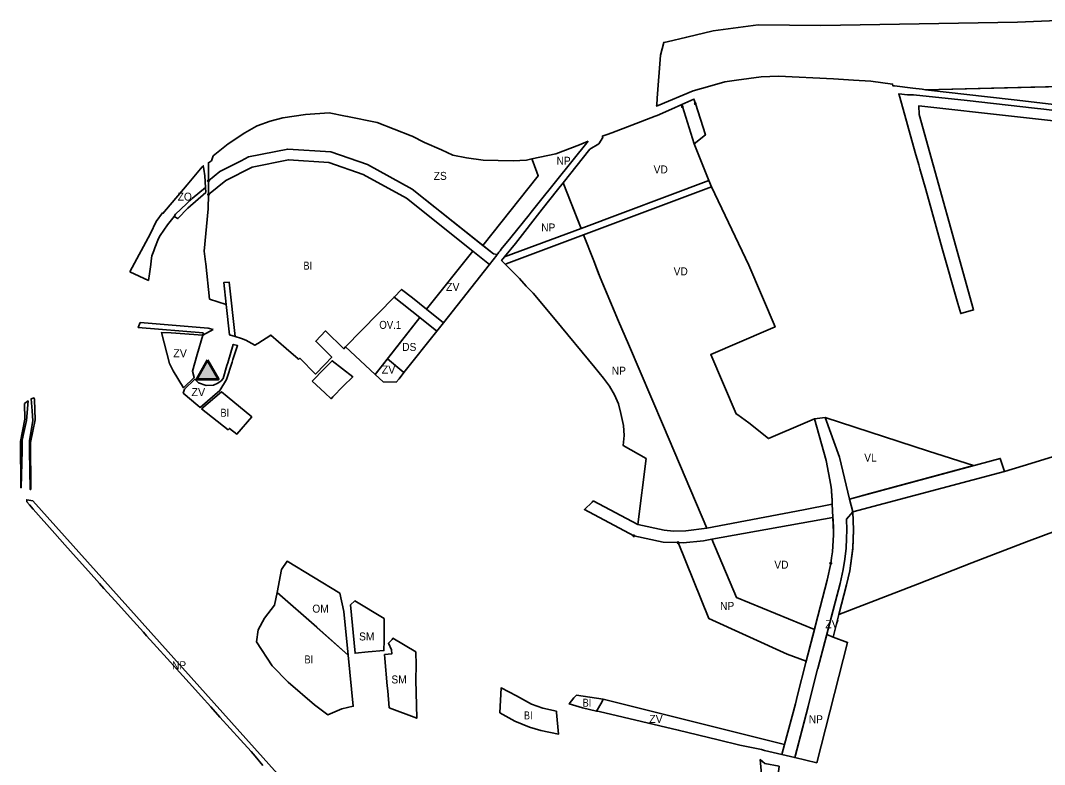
# Model space of a CAD drawing. Extents: x -650276 to -642489, y -1074311 to -1066720.
# Drawn here: x -650276 to -648741, y -1070281 to -1069165 of the extents above; entities that cross this region are included whole.
import ezdxf

# ---------------------------------------------------------------- set-up
doc = ezdxf.new("R2010")
doc.units = 0
doc.header["$LTSCALE"] = 4.8
doc.header["$PDMODE"] = 32
doc.header["$PDSIZE"] = 2.4
for name, color, linetype, lineweight in [('11', 7, 'Continuous', 35), ('12', 7, 'Continuous', 35), ('13', 7, 'Continuous', 35), ('15', 7, 'Continuous', 35), ('18', 7, 'Continuous', 35), ('2', 7, 'Continuous', 35), ('24', 7, 'Continuous', 35), ('25', 7, 'Continuous', 35), ('34', 7, 'Continuous', 35), ('35', 7, 'Continuous', 35), ('40', 7, 'Continuous', 35), ('41', 7, 'Continuous', 35), ('42', 7, 'Continuous', 35), ('48', 7, 'Continuous', 35), ('55', 7, 'Continuous', 53)]:
    doc.layers.add(name, color=color, linetype=linetype, lineweight=lineweight)
doc.layers.add('62', color=7, linetype='Continuous')

msp = doc.modelspace()

# ---------------------------------------------------------------- hatches: boundary and pattern name
at = {"layer": '55'}
msp.add_hatch(color=256, dxfattribs=at).paths.add_polyline_path([(-649995.793, -1069674.354), (-650011.744, -1069703), (-649979.36, -1069703)])

# ---------------------------------------------------------------- linework, layer by layer
at = {"layer": '11'}
msp.add_lwpolyline([(-649788.91, -1069654.4), (-649744.517, -1069695.746), (-649677.124, -1069610.681), (-649715.908, -1069579.804)], close=True, dxfattribs=at)
at = {"layer": '12'}
msp.add_lwpolyline([(-649891.21, -1070022.68), (-649832.007, -1070074.751), (-649784.87, -1070116.76), (-649791.31, -1070051.51), (-649797.45, -1070023.77), (-649876.31, -1069975.93), (-649884.59, -1069988.57)], close=True, dxfattribs=at)
at = {"layer": '13'}
msp.add_lwpolyline([(-648722.24, -1069817.54), (-648772.48, -1069832.83), (-648800.85, -1069841.52), (-649028.017, -1069902.109), (-649027.135, -1069928.902), (-649027.953, -1069955.702), (-649032.644, -1069990.371), (-649037.411, -1070011.659), (-649048.918, -1070055.852), (-648931.057, -1070010.171), (-648849.532, -1069978.559), (-648767.83, -1069946.87), (-648562.242, -1069870.301)], dxfattribs=at)
at = {"layer": '15', "lineweight": 25}
for p, q in [((-649971.446, -1069558.139), (-649963.498, -1069557.234)), ((-649971.446, -1069558.139), (-649967.81, -1069590.74)), ((-649963.498, -1069557.234), (-649954.365, -1069639.105))]:
    msp.add_line(p, q, dxfattribs=at)
at = {"layer": '15'}
msp.add_line((-649057.868, -1069910.51), (-649058.82, -1069890.548), dxfattribs=at)
for points in [[(-648725.82, -1069299.81), (-648741.58, -1069298.16), (-648755.56, -1069296.7), (-648856.68, -1069285.01), (-648937.2, -1069276.37), (-648945.96, -1069276.64), (-648959.11, -1069275.13), (-648957.74, -1069280), (-648934.38, -1069362.79), (-648929.16, -1069381.32), (-648927.37, -1069387.62), (-648927.38, -1069387.623), (-648918.65, -1069418.53), (-648893.86, -1069506.89), (-648870.76, -1069589.26), (-648867.62, -1069599.37), (-648866.17, -1069604.48), (-648847.097, -1069598.995), (-648928.347, -1069306.125), (-648929.112, -1069293.123), (-648642.241, -1069324.949)], [(-649561.17, -1069515.83), (-649566.951, -1069515.099), (-649688.625, -1069418.156), (-649755.971, -1069381.179), (-649810.846, -1069362.154), (-649875.434, -1069357.751), (-649934.363, -1069369.537), (-649945.397, -1069375.277), (-649977.239, -1069391.714), (-649994.329, -1069405.451)], [(-649994.293, -1069425.949), (-649968.465, -1069405.189), (-649929.015, -1069384.784), (-649874.391, -1069373.859)], [(-649874.391, -1069373.859), (-649814.067, -1069377.972), (-649762.488, -1069395.854), (-649697.525, -1069431.522), (-649598.004, -1069510.814), (-649572.972, -1069530.758)], [(-649994.329, -1069405.451), (-649994.329, -1069405.451), (-649994.293, -1069425.949), (-649994.293, -1069425.949)], [(-649431.761, -1069486.57), (-649240.202, -1069414.528), (-649244.08, -1069404.753), (-649435.578, -1069476.772), (-649550.53, -1069519.68)], [(-649548.881, -1069530.963), (-649547.733, -1069530.185), (-649431.761, -1069486.57)], [(-649572.972, -1069530.758), (-649561.91, -1069516.78), (-649561.17, -1069515.83)], [(-649550.53, -1069519.68), (-649554.83, -1069525), (-649551.32, -1069528.49), (-649549.69, -1069530.14), (-649548.881, -1069530.963)], [(-650096.627, -1069617.746), (-650099.55, -1069625.53), (-650002.39, -1069633.65)], [(-649987.49, -1069628.6), (-649994.913, -1069626.246), (-650096.627, -1069617.746)], [(-650002.39, -1069633.65), (-650002.65, -1069637.14), (-649987.49, -1069628.6)], [(-649417.234, -1069885.193), (-649418.94, -1069887.36), (-649430.515, -1069898.514), (-649356.458, -1069937.945)], [(-649246.81, -1069926.27), (-649278.492, -1069930.573), (-649296.851, -1069931.092), (-649310.738, -1069929.342), (-649350.222, -1069920.873), (-649417.234, -1069885.193)], [(-649058.82, -1069890.548), (-649101.89, -1069898.73), (-649246.81, -1069926.27)], [(-649289.95, -1069948.146), (-649282.437, -1069948.342), (-649251.805, -1069945.276), (-649239.635, -1069943.094), (-649057.868, -1069910.51)], [(-649356.458, -1069937.945), (-649312.646, -1069947.342), (-649289.95, -1069948.146)]]:
    msp.add_lwpolyline(points, dxfattribs=at)
for points in [[(-650025.31, -1069446.49), (-649998.512, -1069422.926), (-649999.01, -1069415.628), (-650018.873, -1069431.749), (-650043.521, -1069455.69), (-650045.72, -1069459.1), (-650040.012, -1069461.999)], [(-649967.81, -1069590.74), (-649962.71, -1069636.46), (-649954.365, -1069639.105), (-649963.498, -1069557.234), (-649971.446, -1069558.139)], [(-649677.124, -1069610.681), (-649651.846, -1069630.82), (-649641.978, -1069618.226), (-649667.188, -1069598.14), (-649688.446, -1069581.203), (-649704.646, -1069568.296), (-649715.908, -1069579.804)], [(-648800.85, -1069841.52), (-648806.946, -1069821.79), (-649032.928, -1069882.782), (-649028.017, -1069902.109)]]:
    msp.add_lwpolyline(points, close=True, dxfattribs=at)
for p in [(-649994.329, -1069405.451), (-649994.293, -1069425.949), (-649356.458, -1069937.945), (-649289.95, -1069948.146)]:
    msp.add_point(p, dxfattribs=at)
at = {"layer": '18'}
for points in [[(-649781.53, -1070041.2), (-649774.45, -1070113.92), (-649754.82, -1070111.89), (-649731.12, -1070109.96), (-649730.96, -1070094.91), (-649730.89, -1070088.96), (-649730.6, -1070061.98), (-649774.73, -1070035.58)], [(-649730.57, -1070115.76), (-649730, -1070122.01), (-649726.22, -1070162.75), (-649725.49, -1070170.64), (-649723.17, -1070195.81), (-649682.04, -1070211.58), (-649683.12, -1070154.14), (-649682.98, -1070132.1), (-649683.57, -1070112.05), (-649717.72, -1070091.61), (-649718.71, -1070093.35), (-649724.36, -1070099.03), (-649719.69, -1070108.94), (-649719.24, -1070114.87)]]:
    msp.add_lwpolyline(points, close=True, dxfattribs=at)
at = {"layer": '2'}
for points in [[(-649715.908, -1069579.804), (-649704.646, -1069568.296), (-649688.446, -1069581.203), (-649667.188, -1069598.14), (-649598.004, -1069510.814), (-649697.525, -1069431.522), (-649762.488, -1069395.854), (-649814.067, -1069377.972), (-649874.391, -1069373.859), (-649929.015, -1069384.784), (-649968.465, -1069405.189), (-649994.293, -1069425.949), (-649994.53, -1069447.61), (-650000.59, -1069511.15), (-649998.81, -1069527.07), (-649998.5, -1069529.88), (-649992.59, -1069582.88), (-649967.81, -1069590.74), (-649971.446, -1069558.139), (-649963.498, -1069557.234), (-649954.365, -1069639.105), (-649944.963, -1069642.085)], [(-649944.963, -1069642.085), (-649938.2, -1069644.23), (-649924.8, -1069652.19), (-649920.45, -1069649.53), (-649900.64, -1069636.78), (-649877.82, -1069656.83), (-649859.96, -1069672.53), (-649859.17, -1069673.22), (-649857.49, -1069671.46), (-649833.94, -1069695.24), (-649833.94, -1069695.24), (-649819.98, -1069680.92), (-649809.47, -1069670.13), (-649833.38, -1069646.08), (-649818.71, -1069630.64), (-649791.3, -1069657.21), (-649788.91, -1069654.4), (-649715.908, -1069579.804)]]:
    msp.add_lwpolyline(points, dxfattribs=at)
for points in [[(-649838.99, -1069706.15), (-649820.64, -1069687.33), (-649808.96, -1069675.34), (-649777.94, -1069699.2), (-649792.13, -1069713.65), (-649807.66, -1069729.46), (-649810.41, -1069732.28), (-649819.9, -1069723.61)], [(-650004.59, -1069747.27), (-649974.86, -1069721.96), (-649966.52, -1069728.87), (-649929.38, -1069759.65), (-649951.56, -1069785.42), (-649963, -1069776.7), (-649965, -1069778.7)], [(-649922.3, -1070096.9), (-649919.55, -1070079.01), (-649910.34, -1070061.29), (-649895.45, -1070042.15), (-649891.21, -1070022.68), (-649784.87, -1070116.76), (-649777.29, -1070193.57), (-649794.37, -1070197.2), (-649815.33, -1070206.63), (-649835.28, -1070191.27), (-649874.94, -1070157.19), (-649898.55, -1070132.9)], [(-649557.21, -1070203.53), (-649555.44, -1070165.91), (-649532.57, -1070178.08), (-649509.72, -1070190.24), (-649492.67, -1070196.34), (-649472.6, -1070201.15), (-649472.43, -1070202.9), (-649469.176, -1070235.365), (-649496, -1070230), (-649513, -1070225), (-649535, -1070216)], [(-649442.63, -1070176.69), (-649402.29, -1070182.92), (-649404.2, -1070187.43), (-649412.2, -1070200.71), (-649433.3, -1070195.89), (-649453.27, -1070190.02), (-649446.19, -1070180.76)]]:
    msp.add_lwpolyline(points, close=True, dxfattribs=at)
at = {"layer": '24'}
for p, q in [((-649283.702, -1069294.132), (-649265.774, -1069350.068)), ((-649058.858, -1069889.759), (-649057.868, -1069910.51)), ((-649057.134, -1069932.873), (-649057.868, -1069910.51))]:
    msp.add_line(p, q, dxfattribs=at)
for points in [[(-648721.315, -1069164.952), (-648781.015, -1069167.44), (-649076.02, -1069172.683), (-649169.781, -1069171.432), (-649237.512, -1069180.731), (-649277.021, -1069189.913), (-649306.455, -1069196.754), (-649311.633, -1069197.958), (-649316.47, -1069216.91), (-649321.32, -1069281.47), (-649322.09, -1069291.73), (-649322.22, -1069293.54), (-649319.72, -1069292.47), (-649267.5, -1069270.41), (-649242.5, -1069263.3), (-649220.18, -1069257.03), (-649202.63, -1069254.4), (-649165.62, -1069249.43), (-649139.63, -1069248.73), (-649056.95, -1069252.55), (-649026.955, -1069254.366), (-649001.3, -1069255.92), (-648968.49, -1069260.36), (-648968.05, -1069263.06), (-648965.8, -1069262.75), (-648937.91, -1069266.51), (-648924.13, -1069268.21), (-648918.889, -1069268.875), (-648673.267, -1069262.895)], [(-649264.156, -1069289.589), (-649266.331, -1069282.804), (-649284.695, -1069291.033), (-649283.702, -1069294.132)], [(-649265.774, -1069350.068), (-649249.069, -1069336.66), (-649264.156, -1069289.589)], [(-649061.138, -1069979.243), (-649061.138, -1069979.243), (-649061.139, -1069979.254), (-649066.487, -1070004.267), (-649098.65, -1070127.795), (-649110.925, -1070177.113), (-649114.174, -1070189.816), (-649130.712, -1070250.935), (-649134.294, -1070266.095), (-649115.159, -1070270.568), (-649095.152, -1070193.731), (-649093.095, -1070186.132), (-649095.152, -1070193.731), (-649080.924, -1070137.409), (-649080.38, -1070136.996), (-649047.131, -1070009.304), (-649042.468, -1069988.477), (-649042.468, -1069988.477), (-649039.966, -1069973.035), (-649037.98, -1069956.626), (-649037.322, -1069942.129), (-649037.137, -1069928.996), (-649037.665, -1069912.977), (-649028.017, -1069902.109), (-649032.928, -1069882.782), (-649048, -1069820), (-649069.4, -1069760.67), (-649085.41, -1069762.44), (-649068, -1069825.147), (-649060.897, -1069861.994)]]:
    msp.add_lwpolyline(points, dxfattribs=at)
msp.add_lwpolyline([(-649701.211, -1069692.826), (-649651.773, -1069630.879), (-649677.124, -1069610.681), (-649726.033, -1069672.415)], close=True, dxfattribs=at)
for centre, radius, start, end in [((-649633.43, -1069918.001), 575.266, 2.81398, 5.58706), ((-649347.129, -1069931.193), 290, 350.46253, 4.08974), ((-649347.129, -1069931.193), 290, 359.66809, 4.08974)]:
    msp.add_arc(centre, radius, start, end, dxfattribs=at)
for p in [(-649283.702, -1069294.132), (-649264.156, -1069289.589)]:
    msp.add_point(p, dxfattribs=at)
at = {"layer": '25'}
msp.add_lwpolyline([(-648730.66, -1069290.43), (-648656.242, -1069297.116), (-648673.267, -1069262.895), (-648761.189, -1069265.035), (-648918.889, -1069268.875), (-648909.86, -1069270.02), (-648861.49, -1069275.34), (-648785.92, -1069284.2), (-648730.66, -1069290.43)], close=True, dxfattribs=at)
at = {"layer": '34'}
msp.add_line((-649032.928, -1069882.782), (-649002.558, -1069874.585), dxfattribs=at)
for points in [[(-649002.558, -1069874.585), (-648846.924, -1069832.58), (-648914.48, -1069810.75), (-649069.4, -1069760.67)], [(-649069.4, -1069760.67), (-649048, -1069820), (-649032.928, -1069882.782)]]:
    msp.add_lwpolyline(points, dxfattribs=at)
at = {"layer": '35'}
msp.add_line((-649202.375, -1070030.469), (-649085.737, -1070078.201), dxfattribs=at)
for points in [[(-649283.702, -1069294.132), (-649284.695, -1069291.033), (-649300.133, -1069297.95), (-649321.69, -1069307.61)], [(-649244.08, -1069404.753), (-649265.774, -1069350.068), (-649283.702, -1069294.132)], [(-649321.69, -1069307.61), (-649324.3, -1069308.59), (-649359.48, -1069321.82), (-649389.4, -1069333.35), (-649396.52, -1069336.09), (-649403.92, -1069338.26)], [(-649403.92, -1069338.26), (-649403.03, -1069340.66), (-649408.81, -1069349.89), (-649422.19, -1069357.99), (-649462.25, -1069408.32), (-649435.578, -1069476.772), (-649244.08, -1069404.753)], [(-649060.897, -1069861.994), (-649068, -1069825.147), (-649085.41, -1069762.44), (-649085.41, -1069762.44), (-649099.75, -1069768.575), (-649154.76, -1069792.11), (-649184.05, -1069768.45), (-649200.64, -1069756.53), (-649202.99, -1069754.99), (-649241.11, -1069665.9), (-649155.082, -1069629.097), (-649144.57, -1069624.6), (-649184.1, -1069532.2), (-649240.202, -1069414.528), (-649431.761, -1069486.57), (-649416.52, -1069525.68), (-649409.355, -1069544.517), (-649388.438, -1069594.296), (-649379.32, -1069615.71), (-649364.44, -1069650.55), (-649312.03, -1069773.33)], [(-649312.03, -1069773.33), (-649246.81, -1069926.27), (-649101.89, -1069898.73), (-649058.82, -1069890.548)], [(-649057.868, -1069910.51), (-649239.635, -1069943.094), (-649202.375, -1070030.469)], [(-649085.737, -1070078.201), (-649066.487, -1070004.267), (-649061.139, -1069979.254), (-649061.138, -1069979.243)]]:
    msp.add_lwpolyline(points, dxfattribs=at)
for centre, radius, start, end in [((-649649.71, -1069919.176), 591.583, 2.77379, 5.54687), ((-649347.129, -1069931.193), 290, 350.46253, 4.08974)]:
    msp.add_arc(centre, radius, start, end, dxfattribs=at)
msp.add_point((-649061.138, -1069979.243), dxfattribs=at)
at = {"layer": '40'}
for points in [[(-649667.188, -1069598.14), (-649641.978, -1069618.226), (-649572.972, -1069530.758), (-649598.004, -1069510.814)], [(-650002.65, -1069637.14), (-650050.26, -1069633.65), (-650064.77, -1069633.06), (-650052.88, -1069679.49), (-650047.45, -1069690.69), (-650031.64, -1069715.9), (-650015.53, -1069700.21), (-650018.31, -1069690.89), (-650011.15, -1069665.82)], [(-649998, -1069712.26), (-650009.509, -1069708.678), (-650014.74, -1069702.9), (-650030.26, -1069717.96), (-650032.13, -1069723.75), (-650010.04, -1069742.58), (-650006.85, -1069745.3), (-649977.31, -1069720.05), (-649967.27, -1069703.29), (-649958.87, -1069677.59), (-649957.54, -1069673.5), (-649950.69, -1069652.54), (-649957.15, -1069650.76), (-649965.45, -1069678.6), (-649966.59, -1069682.44), (-649972.35, -1069701.78), (-649975.45, -1069705.65), (-649980.22, -1069709.07), (-649986.69, -1069712.03)], [(-649732.52, -1069706.92), (-649712.64, -1069707.43), (-649708.322, -1069702.293), (-649701.211, -1069692.826), (-649726.033, -1069672.415), (-649744.517, -1069695.746)], [(-649060.411, -1070060.306), (-649067.061, -1070085.844), (-649057.722, -1070089.665), (-649048.918, -1070055.852), (-649037.411, -1070011.659), (-649032.644, -1069990.371), (-649028.007, -1069957.455), (-649027.135, -1069928.902), (-649028.017, -1069902.109), (-649037.665, -1069912.977), (-649037.137, -1069928.996), (-649037.322, -1069942.129), (-649037.98, -1069956.626), (-649039.966, -1069973.035), (-649042.468, -1069988.477), (-649047.131, -1070009.304)], [(-649160.748, -1070243.413), (-649402.29, -1070182.92), (-649404.2, -1070187.43), (-649412.2, -1070200.71), (-649412.2, -1070200.71), (-649408.24, -1070201.62), (-649372.69, -1070209.74), (-649289.83, -1070229.16), (-649229.8, -1070243.94), (-649197.55, -1070251.65), (-649164.91, -1070258.55), (-649160.54, -1070259.96), (-649134.294, -1070266.095), (-649130.712, -1070250.935)], [(-649138.43, -1070283.6), (-649159.78, -1070279.52), (-649166.86, -1070273.48), (-649162.91, -1070317.47), (-649159.19, -1070358.82), (-649153.64, -1070382.9), (-649148.23, -1070382.48), (-649143.633, -1070382.123), (-649146.163, -1070347.543)]]:
    msp.add_lwpolyline(points, close=True, dxfattribs=at)
at = {"layer": '41'}
msp.add_lwpolyline([(-649934.363, -1069369.537), (-649875.434, -1069357.751), (-649810.846, -1069362.154), (-649755.971, -1069381.179), (-649688.625, -1069418.156), (-649582.972, -1069502.334), (-649499.761, -1069397.905), (-649507.61, -1069377.35), (-649509.42, -1069372.61), (-649517.17, -1069374.3), (-649537.32, -1069375.23), (-649582.25, -1069374.51), (-649607.18, -1069370.92), (-649627.76, -1069366.8), (-649645.03, -1069358.8), (-649670.23, -1069347.9), (-649688.73, -1069338.7), (-649690.59, -1069337.98), (-649741.5, -1069317.74), (-649785.8, -1069308.94), (-649789, -1069308.31), (-649813.3, -1069303.66), (-649848.62, -1069305.95), (-649882.93, -1069311.1), (-649901.58, -1069316.01), (-649921.54, -1069323.03), (-649922.11, -1069323.35), (-649939.81, -1069333.47), (-649964.53, -1069350.02), (-649987.12, -1069368.03), (-649989.67, -1069375.36), (-649994.38, -1069378.33), (-649994.35, -1069394.43), (-649994.34, -1069398.8), (-649994.329, -1069405.451), (-649977.239, -1069391.714), (-649945.397, -1069375.277)], close=True, dxfattribs=at)
at = {"layer": '42'}
msp.add_lwpolyline([(-650112.18, -1069542.11), (-650081.29, -1069484.35), (-650072.5, -1069466.44), (-650063.12, -1069453.54), (-650062.17, -1069454.05), (-650060.29, -1069451.7), (-650057.49, -1069448.18), (-650026.33, -1069411.47), (-650003.73, -1069384.71), (-650002.11, -1069382.8), (-650001.13, -1069388.13), (-649999.95, -1069397.98), (-649999.01, -1069415.628), (-650018.873, -1069431.749), (-650043.521, -1069455.69), (-650045.72, -1069459.1), (-650055.612, -1069471.639), (-650066.897, -1069487.541), (-650069.369, -1069492.132), (-650074.75, -1069506.133), (-650076.365, -1069510.333), (-650079.264, -1069517.874), (-650080.302, -1069525.418), (-650080.802, -1069530.768), (-650082.963, -1069544.736), (-650084.345, -1069554.773)], close=True, dxfattribs=at)
at = {"layer": '48'}
msp.add_line((-649499.761, -1069397.905), (-649582.972, -1069502.334), dxfattribs=at)
for points in [[(-649561.17, -1069515.83), (-649560.54, -1069515.02), (-649558.71, -1069512.62), (-649556.9, -1069510.24), (-649555.16, -1069508.07), (-649540.81, -1069490.25), (-649513.66, -1069456.53), (-649510.56, -1069452.67), (-649498.47, -1069437.65), (-649424.8, -1069346.14)], [(-649424.8, -1069346.14), (-649438.17, -1069351.27), (-649473.35, -1069364.76), (-649473.35, -1069364.76), (-649509.42, -1069372.61), (-649507.61, -1069377.35), (-649499.761, -1069397.905)], [(-649493.94, -1069448.14), (-649534.06, -1069499.33), (-649550.53, -1069519.68), (-649435.578, -1069476.772), (-649440.466, -1069464.229), (-649462.25, -1069408.32)], [(-649462.25, -1069408.32), (-649470.71, -1069418.95), (-649493.94, -1069448.14), (-649493.94, -1069448.14)], [(-649582.972, -1069502.334), (-649566.951, -1069515.099), (-649561.17, -1069515.83)], [(-649843.513, -1070347.685), (-650257.713, -1069885.547), (-650266.89, -1069883.7), (-650266.68, -1069886.78), (-650262.64, -1069891.57), (-650257.16, -1069898.07), (-650224.71, -1069934.41), (-650209.51, -1069951.43), (-650192.51, -1069970.47), (-650174.3, -1069990.86), (-650157.87, -1070009.26), (-650151.03, -1070016.84), (-650134.26, -1070035.45), (-650106.76, -1070065.96), (-650091.89, -1070082.46), (-650087.18, -1070087.68), (-650076.72, -1070099.29), (-650051.33, -1070127.45), (-650037.78, -1070142.48), (-650018.41, -1070163.97), (-650005.3, -1070178.51), (-649990.95, -1070194.43), (-649977.05, -1070209.85), (-649946.39, -1070243.87), (-649930.46, -1070261.54), (-649924.15, -1070268.55), (-649913.03, -1070282.44)], [(-649114.172, -1070266.777), (-649114.931, -1070270.621), (-649082.233, -1070278.265), (-649036.031, -1070097.854), (-649057.722, -1070089.665), (-649067.061, -1070085.844)], [(-649067.061, -1070085.844), (-649080.38, -1070136.996), (-649080.872, -1070137.369), (-649083.108, -1070146.053)], [(-649083.108, -1070146.053), (-649095.152, -1070193.731), (-649093.095, -1070186.132), (-649095.152, -1070193.731), (-649114.172, -1070266.777)]]:
    msp.add_lwpolyline(points, dxfattribs=at)
for points in [[(-649392.85, -1069713.53), (-649385.25, -1069726.48), (-649379.49, -1069740.04), (-649376.01, -1069754.58), (-649372.2, -1069772.58), (-649370.94, -1069787.45), (-649372.56, -1069802.33), (-649372.56, -1069802.33), (-649338, -1069822), (-649350.222, -1069920.873), (-649310.738, -1069929.342), (-649296.851, -1069931.092), (-649278.492, -1069930.573), (-649246.81, -1069926.27), (-649312.03, -1069773.33), (-649364.44, -1069650.55), (-649379.32, -1069615.71), (-649407.002, -1069550.701), (-649416.52, -1069525.68), (-649431.761, -1069486.57), (-649547.733, -1069530.185), (-649548.881, -1069530.963), (-649538.49, -1069541.54), (-649527.84, -1069552.16), (-649517.81, -1069563.27), (-649507.23, -1069573.85), (-649474.46, -1069613.59), (-649415.12, -1069685.26), (-649401.77, -1069701.47)], [(-650260.645, -1069868.536), (-650260.748, -1069867.327), (-650261.204, -1069797.969), (-650254.411, -1069764.006), (-650255.21, -1069733.253), (-650255.716, -1069731.162), (-650259.97, -1069732.29), (-650258.74, -1069750.62), (-650257.77, -1069765.2), (-650262.93, -1069794.84), (-650262.77, -1069805.54), (-650262.7, -1069809.89), (-650261.8, -1069868.33)], [(-650270.059, -1069739.232), (-650269.449, -1069762.714), (-650276.214, -1069796.532), (-650275.76, -1069865.474), (-650274.95, -1069865.62), (-650273.87, -1069809.74), (-650273.78, -1069805.2), (-650273.58, -1069794.48), (-650270.15, -1069778.65), (-650267.22, -1069765.1), (-650265.37, -1069741.61), (-650264.91, -1069735.69)], [(-649251.805, -1069945.276), (-649282.437, -1069948.342), (-649289.95, -1069948.146), (-649243.846, -1070062.071), (-649126.437, -1070115.217), (-649126.437, -1070115.217), (-649098.101, -1070125.688), (-649085.737, -1070078.201), (-649202.375, -1070030.469), (-649239.635, -1069943.094)]]:
    msp.add_lwpolyline(points, close=True, dxfattribs=at)
at = {"layer": '55'}
msp.add_lwpolyline([(-649995.793, -1069674.354), (-650011.744, -1069703), (-649979.36, -1069703)], close=True, dxfattribs=at)

# ---------------------------------------------------------------- texts
at = {"layer": '62'}
for s, width, p in [('NP', 0.95, (-649472.389, -1069381.42)), ('ZS', 0.95, (-649656.482, -1069404.05)), ('VD', 0.95, (-649326.761, -1069394.352)), ('ZO', 0.95, (-650040.423, -1069435.188)), ('NP', 0.95, (-649495.389, -1069481.42)), ('BI', 0.85, (-649851.88, -1069538.658)), ('VD', 0.95, (-649296.767, -1069547.204)), ('OV.1', 0.9, (-649738.147, -1069627.487)), ('DS', 0.95, (-649703.778, -1069660.629)), ('NP', 0.95, (-649389.556, -1069696.287)), ('BI', 0.85, (-649976.221, -1069759.292)), ('VL', 0.95, (-649010.928, -1069826.6)), ('VD', 0.95, (-649145.767, -1069987.204)), ('NP', 0.95, (-649227.076, -1070049.026)), ('OM', 0.95, (-649838.604, -1070053.132)), ('SM', 0.95, (-649768.411, -1070094.846)), ('NP', 0.95, (-650048.985, -1070137.967)), ('BI', 0.85, (-649850.221, -1070129.292)), ('SM', 0.95, (-649719.964, -1070159.337)), ('BI', 0.85, (-649433.221, -1070194.292)), ('BI', 0.85, (-649521.221, -1070213.292)), ('NP', 0.95, (-649094.076, -1070219.026))]:
    msp.add_text(s, height=12, dxfattribs=dict(at, width=width)).set_placement(p)
for p in [(-649638.283, -1069570.48), (-650047.124, -1069669.988), (-649734.572, -1069694.498), (-650019.82, -1069728.32), (-649069.527, -1070076.528), (-649333.527, -1070218.528)]:
    msp.add_text('ZV', height=12, dxfattribs=at).set_placement(p)

doc.saveas('drawing.dxf')
